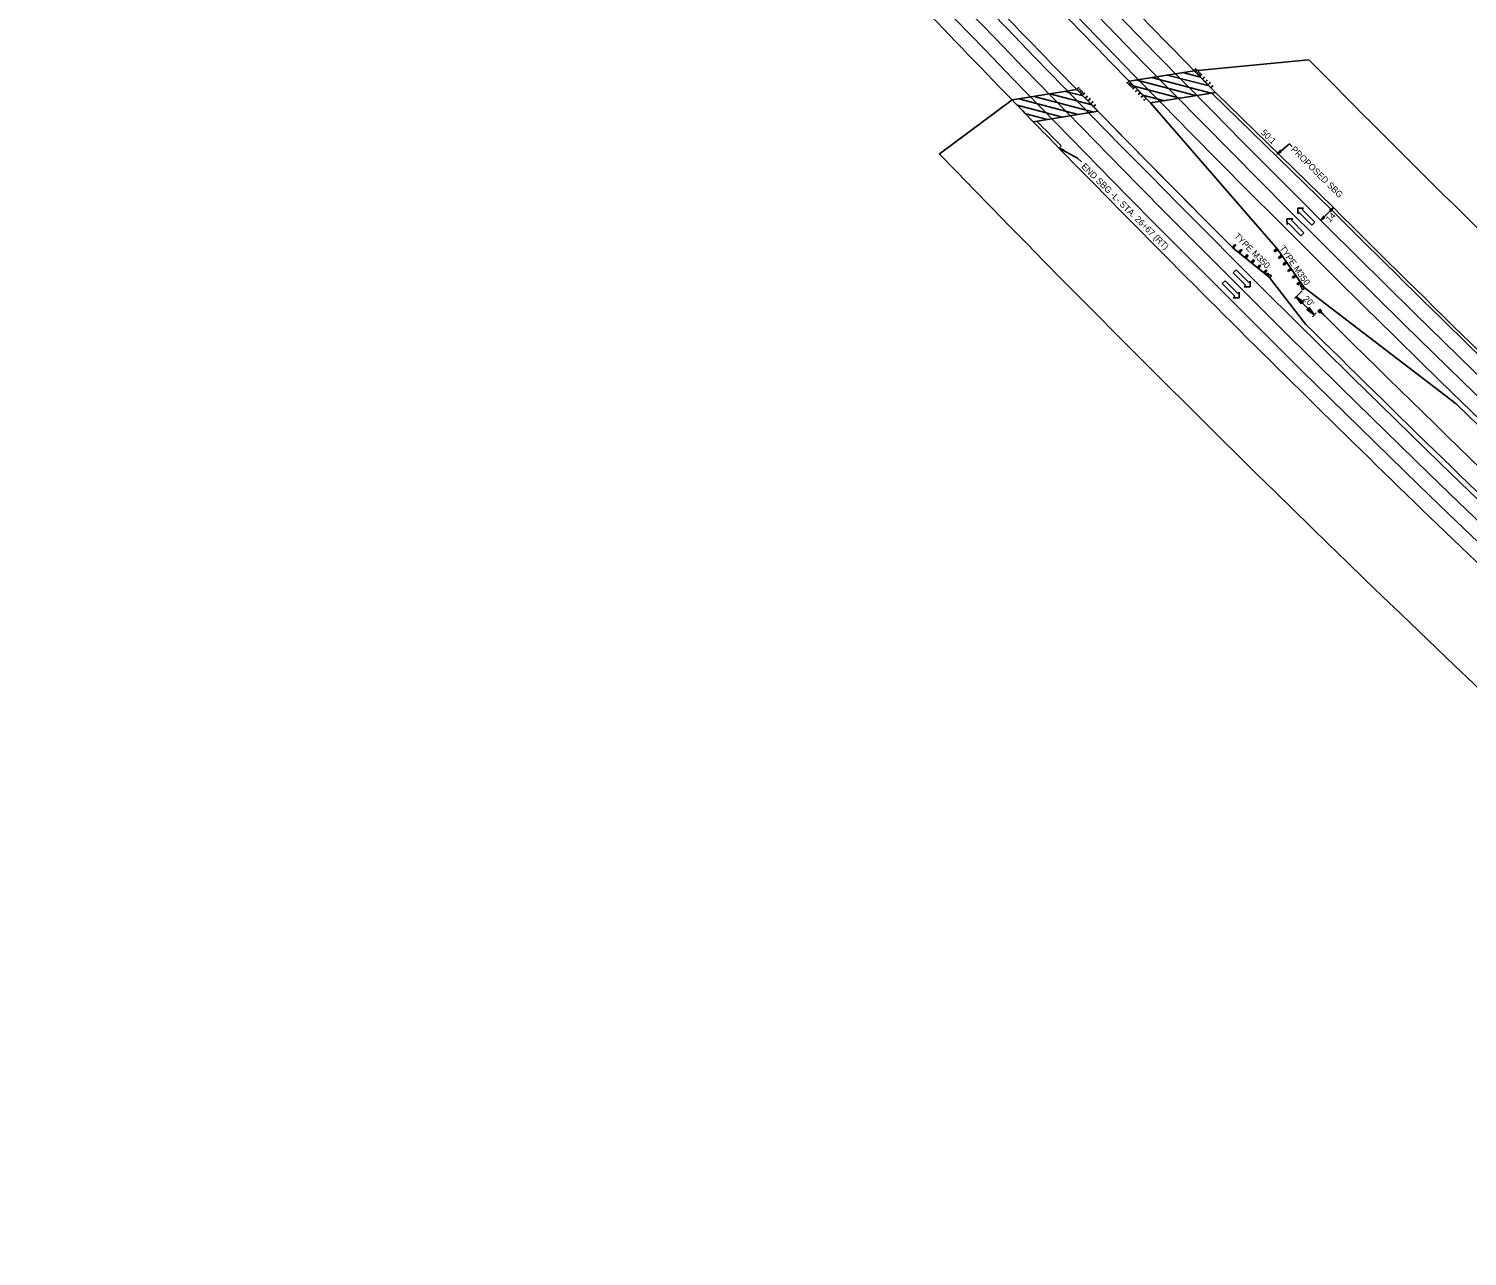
# Model space of a CAD drawing. Extents: x 1602193 to 1605074, y 908180 to 910630.
# Drawn here: x 1602527 to 1603654, y 908258 to 909219 of the extents above; entities that cross this region are included whole.
import ezdxf

# ---------------------------------------------------------------- set-up
doc = ezdxf.new("R2010")
doc.units = 0
for name, color, linetype in [('Prop Approach Slab', 7, 'Continuous'), ('Prop Approach Slab Hatching', 7, 'Continuous'), ('Prop Cable Guiderail Anchor Unit CELL', 7, 'Continuous'), ('Prop Cable Guiderail Double Face', 7, 'Continuous'), ('Prop Conc Shoulder Berm Gutter', 7, 'Continuous'), ('Prop Dimension', 7, 'Continuous'), ('Prop Dimension Text', 7, 'Continuous'), ('Prop DSN Text', 7, 'Continuous'), ('Prop EOT', 7, 'Continuous'), ('Prop Fence Woven Wire', 7, 'Continuous'), ('Prop Guardrail', 7, 'Continuous'), ('Prop Guardrail Anchor Unit CELL', 7, 'Continuous'), ('Prop Lane Arrow CELL', 7, 'Continuous'), ('Prop Lane Lines', 7, 'Continuous'), ('Prop Paved Shoulder', 7, 'Continuous'), ('Prop Roadway Bridge', 7, 'Continuous'), ('Prop Structure Anchor Unit CELL', 7, 'Continuous'), ('Prop Terminator CELL', 7, 'Continuous')]:
    doc.layers.add(name, color=color, linetype=linetype)

msp = doc.modelspace()

# ---------------------------------------------------------------- linework, layer by layer
at = {"layer": 'Prop Approach Slab'}
for p, q in [((1603456.6, 909169.3), (1603405.8, 909161.1)), ((1603364.7, 909154.5), (1603314, 909146.3))]:
    msp.add_line(p, q, dxfattribs=at)
for radius, start, end in [(14299.9, 224.45944, 224.55525), (14341.9, 224.34066, 224.43605), (14417.9, 224.12792, 224.22258), (14375.9, 224.24514, 224.34021)]:
    msp.add_arc((1613646.3, 919202), radius, start, end, dxfattribs=at)
at = {"layer": 'Prop Approach Slab Hatching'}
for p, q in [((1603392.9, 909174.2), (1603428.8, 909164.8)), ((1603394.3, 909179), (1603441, 909166.8)), ((1603406.5, 909181), (1603453.2, 909168.7)), ((1603418.7, 909182.9), (1603451.6, 909174.3)), ((1603431, 909184.9), (1603444.8, 909181.3)), ((1603302.5, 909164.2), (1603349.2, 909152)), ((1603314.7, 909166.2), (1603361.4, 909153.9)), ((1603326.9, 909168.1), (1603359.7, 909159.5)), ((1603339.1, 909170.1), (1603352.9, 909166.5)), ((1603399.7, 909167.2), (1603416.6, 909162.8)), ((1603301.2, 909159.4), (1603336.9, 909150)), ((1603308, 909152.4), (1603324.7, 909148))]:
    msp.add_line(p, q, dxfattribs=at)
at = {"layer": 'Prop Cable Guiderail Anchor Unit CELL'}
for p, q in [((1603536.9, 908998), (1603538.3, 908999.4)), ((1603536.9, 908998), (1603538.4, 908996.6)), ((1603537.9, 908997.9), (1603538.5, 908998.5)), ((1603537.9, 908997.9), (1603538.2, 908997.5)), ((1603538.2, 908997.5), (1603538.8, 908998.1)), ((1603544, 908992.4), (1603538.2, 908997.9)), ((1603538.3, 908999.4), (1603539.8, 908998)), ((1603544, 908992.4), (1603538.3, 908998)), ((1603538.4, 908996.6), (1603539.8, 908998)), ((1603538.5, 908998.5), (1603538.8, 908998.1)), ((1603544, 908992.4), (1603538.5, 908998.1)), ((1603555.4, 908981.1), (1603544, 908992.4)), ((1603544, 908992.4), (1603544, 908992.4))]:
    msp.add_line(p, q, dxfattribs=at)
at = {"layer": 'Prop Cable Guiderail Double Face'}
msp.add_arc((1613646.3, 919202), 14362.9, 225.3666, 228.62871, dxfattribs=at)
at = {"layer": 'Prop Conc Shoulder Berm Gutter'}
msp.add_line((1603456.6, 909169.3), (1603549.1, 909079), dxfattribs=at)
for radius, start, end in [(14417.9, 224.22258, 224.33714), (14297.9, 225.07288, 227.66114)]:
    msp.add_arc((1613646.3, 919202), radius, start, end, dxfattribs=at)
at = {"layer": 'Prop Dimension'}
for p, q in [((1603524.4, 909013.8), (1603518.4, 909007.8)), ((1603535.5, 908996.6), (1603532.6, 908993.6))]:
    msp.add_line(p, q, dxfattribs=at)
msp.add_arc((1613646.3, 919202), 14368, 225.18707, 225.26688, dxfattribs=at)
at = {"layer": 'Prop Dimension Text'}
msp.add_line((1603539.2, 909069.1), (1603549.1, 909079), dxfattribs=at)
at = {"layer": 'Prop DSN Text'}
for p, q in [((1603504.9, 909121), (1603514.6, 909129)), ((1603514.6, 909129), (1603516.7, 909127)), ((1603334.1, 909125.7), (1603348.6, 909117.8)), ((1603351.7, 909114.8), (1603348.6, 909117.8))]:
    msp.add_line(p, q, dxfattribs=at)
for points in [[(1603337.1, 909123.3), (1603334.1, 909125.7), (1603337.7, 909124.4), (1603337, 909124.1)], [(1603508.3, 909122.9), (1603504.9, 909121), (1603507.4, 909123.9), (1603507.5, 909123.1)], [(1603545.9, 909076.8), (1603549.1, 909079), (1603546.8, 909075.9), (1603546.7, 909076.7)], [(1603542.3, 909071.3), (1603539.2, 909069.1), (1603541.4, 909072.3), (1603541.5, 909071.5)]]:
    msp.add_lwpolyline(points, close=True, dxfattribs=at)
at = {"layer": 'Prop EOT'}
for radius, start, end in [(14311.9, 219.48088, 227.66114), (14335.9, 219.48098, 227.66104), (14381.9, 219.48098, 227.66104), (14405.9, 219.47972, 227.6623)]:
    msp.add_arc((1613646.3, 919202), radius, start, end, dxfattribs=at)
at = {"layer": 'Prop Fence Woven Wire'}
for p, q in [((1603439.8, 909186.3), (1603529.6, 909194.9)), ((1603297.4, 909163.4), (1603240.2, 909121))]:
    msp.add_line(p, q, dxfattribs=at)
for centre, radius, start, end in [((1613600.3, 919154.7), 14163.9, 224.68305, 227.26896), ((1613603.1, 919154.1), 14423.9, 224.0735, 229.06345)]:
    msp.add_arc(centre, radius, start, end, dxfattribs=at)
at = {"layer": 'Prop Guardrail'}
for p, q in [((1603549.1, 909079), (1603456.6, 909169.3)), ((1603405.8, 909161.1), (1603505.1, 909046.5))]:
    msp.add_line(p, q, dxfattribs=at)
for radius, start, end in [(14341.9, 224.41557, 224.43605), (14299.9, 224.53456, 224.55525), (14375.9, 224.31987, 224.939), (14297.9, 225.07288, 227.66114)]:
    msp.add_arc((1613646.3, 919202), radius, start, end, dxfattribs=at)
at = {"layer": 'Prop Guardrail Anchor Unit CELL'}
for p, q in [((1603469.8, 909047.9), (1603471.7, 909050.2)), ((1603471.6, 909048.4), (1603471.7, 909050.2)), ((1603471.7, 909050.2), (1603472.5, 909049.5)), ((1603469.8, 909047.9), (1603471.6, 909048.4)), ((1603470.2, 909047.6), (1603496.9, 909026)), ((1603470.6, 909047.2), (1603472.5, 909049.5)), ((1603470.8, 909049), (1603470.6, 909047.2)), ((1603472.5, 909049.5), (1603470.8, 909049)), ((1603470.8, 909049), (1603471.6, 909048.4)), ((1603474.7, 909043.9), (1603476.6, 909046.2)), ((1603474.7, 909043.9), (1603476.5, 909044.4)), ((1603475.5, 909043.3), (1603477.4, 909045.6)), ((1603475.7, 909045.1), (1603475.5, 909043.3)), ((1603477.4, 909045.6), (1603475.7, 909045.1)), ((1603475.7, 909045.1), (1603476.5, 909044.4)), ((1603476.5, 909044.4), (1603476.6, 909046.2)), ((1603476.6, 909046.2), (1603477.4, 909045.6)), ((1603479.6, 909039.9), (1603481.5, 909042.2)), ((1603479.6, 909039.9), (1603481.3, 909040.5)), ((1603480.4, 909039.3), (1603482.3, 909041.6)), ((1603480.6, 909041.1), (1603480.4, 909039.3)), ((1603482.3, 909041.6), (1603480.6, 909041.1)), ((1603480.6, 909041.1), (1603481.3, 909040.5)), ((1603481.3, 909040.5), (1603481.5, 909042.2)), ((1603481.5, 909042.2), (1603482.3, 909041.6)), ((1603504.8, 909046.9), (1603502.4, 909045.2)), ((1603504.2, 909045.2), (1603502.4, 909045.2)), ((1603502.4, 909045.2), (1603503, 909044.4)), ((1603505.4, 909046.1), (1603503, 909044.4)), ((1603503, 909044.4), (1603503.6, 909046)), ((1603503.6, 909046), (1603505.4, 909046.1)), ((1603503.6, 909046), (1603504.2, 909045.2)), ((1603504.8, 909046.9), (1603504.2, 909045.2)), ((1603505.1, 909046.5), (1603524.7, 909018.3)), ((1603508.4, 909041.7), (1603506, 909040)), ((1603507.8, 909040), (1603506, 909040)), ((1603506, 909040), (1603506.6, 909039.2)), ((1603509, 909040.9), (1603506.6, 909039.2)), ((1603506.6, 909039.2), (1603507.2, 909040.8)), ((1603507.2, 909040.8), (1603509, 909040.9)), ((1603507.2, 909040.8), (1603507.8, 909040)), ((1603508.4, 909041.7), (1603507.8, 909040)), ((1603484.5, 909036), (1603486.4, 909038.3)), ((1603484.5, 909036), (1603486.2, 909036.5)), ((1603485.3, 909035.4), (1603487.1, 909037.6)), ((1603485.5, 909037.1), (1603485.3, 909035.4)), ((1603487.1, 909037.6), (1603485.5, 909037.1)), ((1603485.5, 909037.1), (1603486.2, 909036.5)), ((1603486.2, 909036.5), (1603486.4, 909038.3)), ((1603486.4, 909038.3), (1603487.1, 909037.6)), ((1603489.4, 909032), (1603491.3, 909034.3)), ((1603489.4, 909032), (1603491.1, 909032.6)), ((1603490.2, 909031.4), (1603492, 909033.7)), ((1603490.4, 909033.2), (1603490.2, 909031.4)), ((1603492, 909033.7), (1603490.4, 909033.2)), ((1603490.4, 909033.2), (1603491.1, 909032.6)), ((1603491.1, 909032.6), (1603491.3, 909034.3)), ((1603491.3, 909034.3), (1603492, 909033.7)), ((1603494.3, 909028.1), (1603496.2, 909030.3)), ((1603494.3, 909028.1), (1603496, 909028.6)), ((1603494.7, 909027.7), (1603495.2, 909028.3)), ((1603495.1, 909027.4), (1603496.9, 909029.7)), ((1603495.3, 909029.2), (1603495.1, 909027.4)), ((1603496.9, 909029.7), (1603495.3, 909029.2)), ((1603495.3, 909029.2), (1603496, 909028.6)), ((1603496, 909028.6), (1603496.2, 909030.3)), ((1603496.2, 909030.3), (1603496.9, 909029.7)), ((1603497.4, 909027.7), (1603496.4, 909026.4)), ((1603498.5, 909026.8), (1603497.4, 909027.7)), ((1603497.4, 909025.5), (1603497.4, 909027.7)), ((1603512, 909036.5), (1603509.6, 909034.9)), ((1603511.4, 909034.9), (1603509.6, 909034.9)), ((1603509.6, 909034.9), (1603510.2, 909034)), ((1603512.6, 909035.7), (1603510.2, 909034)), ((1603510.2, 909034), (1603510.8, 909035.7)), ((1603510.8, 909035.7), (1603511.4, 909034.9)), ((1603510.8, 909035.7), (1603512.6, 909035.7)), ((1603512, 909036.5), (1603511.4, 909034.9)), ((1603515.6, 909031.4), (1603513.2, 909029.7)), ((1603515, 909029.7), (1603513.2, 909029.7)), ((1603513.2, 909029.7), (1603513.8, 909028.9)), ((1603516.2, 909030.5), (1603513.8, 909028.9)), ((1603513.8, 909028.9), (1603514.4, 909030.5)), ((1603514.4, 909030.5), (1603515, 909029.7)), ((1603514.4, 909030.5), (1603516.2, 909030.5)), ((1603515.6, 909031.4), (1603515, 909029.7)), ((1603496.4, 909026.4), (1603498.5, 909026.8)), ((1603496.9, 909026), (1603497.4, 909026.6)), ((1603496.9, 909026), (1603498.6, 909024.6)), ((1603497.4, 909025.5), (1603498.5, 909026.8)), ((1603497.4, 909025.5), (1603497.9, 909026.1)), ((1603497.4, 909025.5), (1603497.9, 909026.1)), ((1603499, 909026.3), (1603497.9, 909026.1)), ((1603519.2, 909026.2), (1603516.8, 909024.5)), ((1603518.6, 909024.5), (1603516.8, 909024.5)), ((1603516.8, 909024.5), (1603517.4, 909023.7)), ((1603519.8, 909025.4), (1603517.4, 909023.7)), ((1603517.4, 909023.7), (1603518, 909025.3)), ((1603518, 909025.3), (1603519.8, 909025.4)), ((1603518, 909025.3), (1603518.6, 909024.5)), ((1603519.2, 909026.2), (1603518.6, 909024.5)), ((1603522.8, 909021), (1603520.4, 909019.3)), ((1603522.2, 909019.3), (1603520.4, 909019.3)), ((1603520.4, 909019.3), (1603521, 909018.5)), ((1603523.4, 909020.2), (1603521, 909018.5)), ((1603521, 909018.5), (1603521.6, 909020.2)), ((1603521.6, 909020.2), (1603522.2, 909019.3)), ((1603521.6, 909020.2), (1603523.4, 909020.2)), ((1603522.8, 909021), (1603522.2, 909019.3)), ((1603523.1, 909020.6), (1603522.5, 909020.2)), ((1603523, 909018), (1603524.3, 909018.9)), ((1603523.8, 909016.8), (1603523, 909018)), ((1603525.1, 909017.7), (1603523, 909018)), ((1603524.3, 909018.9), (1603523.8, 909016.8)), ((1603525.1, 909017.7), (1603523.8, 909016.8)), ((1603524.7, 909018.3), (1603524, 909017.8)), ((1603524.2, 909016.2), (1603524.5, 909017.3)), ((1603525.1, 909017.7), (1603524.5, 909017.3)), ((1603525.1, 909017.7), (1603524.5, 909017.3)), ((1603524.7, 909018.3), (1603526, 909016.5))]:
    msp.add_line(p, q, dxfattribs=at)
for centre, major_axis, start_param, end_param in [((1603499.2, 909025.4), (0.625, 0.772), 3.141593, 7.214552), ((1603525.1, 909015.9), (0.815, 0.567), 2.210226, 6.283185)]:
    msp.add_ellipse(centre, major_axis=major_axis, ratio=0.995379, start_param=start_param, end_param=end_param, dxfattribs=at)
at = {"layer": 'Prop Lane Arrow CELL'}
for p, q in [((1603521.1, 909074.3), (1603521.1, 909078.7)), ((1603521.1, 909078.7), (1603525.6, 909078.7)), ((1603522.2, 909075.3), (1603521.1, 909074.3)), ((1603532.1, 909065.4), (1603522.2, 909075.3)), ((1603525.6, 909078.7), (1603524.5, 909077.6)), ((1603524.5, 909077.6), (1603534.4, 909067.7)), ((1603512.7, 909065.8), (1603512.6, 909070.2)), ((1603512.6, 909070.2), (1603517.1, 909070.2)), ((1603513.7, 909066.8), (1603512.7, 909065.8)), ((1603523.6, 909056.9), (1603513.7, 909066.8)), ((1603517.1, 909070.2), (1603516.1, 909069.2)), ((1603516.1, 909069.2), (1603525.9, 909059.2)), ((1603534.4, 909067.7), (1603532.1, 909065.4)), ((1603525.9, 909059.2), (1603523.6, 909056.9)), ((1603470.4, 909028), (1603472.8, 909030.3)), ((1603480.3, 909018.1), (1603470.4, 909028)), ((1603472.8, 909030.3), (1603482.7, 909020.4)), ((1603461.8, 909019.5), (1603464.2, 909021.8)), ((1603471.7, 909009.6), (1603461.8, 909019.5)), ((1603464.2, 909021.8), (1603474, 909011.9)), ((1603479.2, 909017), (1603480.3, 909018.1)), ((1603483.7, 909017.1), (1603479.2, 909017)), ((1603482.7, 909020.4), (1603483.7, 909021.5)), ((1603483.7, 909021.5), (1603483.7, 909017.1)), ((1603470.6, 909008.5), (1603471.7, 909009.6)), ((1603475.1, 909008.5), (1603470.6, 909008.5)), ((1603474, 909011.9), (1603475.1, 909012.9)), ((1603475.1, 909012.9), (1603475.1, 909008.5))]:
    msp.add_line(p, q, dxfattribs=at)
at = {"layer": 'Prop Lane Lines'}
for radius in [14323.9, 14393.9]:
    msp.add_arc((1613646.3, 919202), radius, 219.48098, 227.66104, dxfattribs=at)
at = {"layer": 'Prop Paved Shoulder'}
for p, q in [((1603453.7, 909168.8), (1603547.4, 909077.4)), ((1603405.8, 909161.1), (1603505.1, 909046.5)), ((1603334.1, 909125.7), (1603335.7, 909127.3)), ((1603470.2, 909047.6), (1603498.6, 909024.6)), ((1603505.1, 909046.5), (1603526, 909016.5)), ((1603498.6, 909024.6), (1603527.5, 908987.6)), ((1603526, 909016.5), (1603645.1, 908925.4))]:
    msp.add_line(p, q, dxfattribs=at)
for radius, start, end in [(14375.9, 224.34021, 224.939), (14415.5, 224.22909, 224.33714), (14417.9, 224.33714, 226.46447), (14300.2, 225.07288, 227.66104), (14377.9, 225.26931, 227.66083), (14339.9, 225.77799, 227.66104)]:
    msp.add_arc((1613646.3, 919202), radius, start, end, dxfattribs=at)
at = {"layer": 'Prop Roadway Bridge'}
for p, q in [((1603439.8, 909186.3), (1603389.1, 909178.1)), ((1603348, 909171.5), (1603297.4, 909163.4))]:
    msp.add_line(p, q, dxfattribs=at)
for radius, start, end in [(14299.9, 224.00576, 224.45944), (14375.9, 223.79503, 224.24514), (14341.9, 223.88896, 224.34066), (14417.9, 223.67976, 224.12792)]:
    msp.add_arc((1613646.3, 919202), radius, start, end, dxfattribs=at)
at = {"layer": 'Prop Structure Anchor Unit CELL'}
for p, q in [((1603439.8, 909186.3), (1603441.3, 909187.7)), ((1603439.8, 909186.3), (1603453, 909172.9)), ((1603440.9, 909188.1), (1603441.7, 909187.3)), ((1603440.9, 909185.2), (1603442.4, 909186.6)), ((1603442, 909187), (1603442.8, 909186.2)), ((1603442, 909184.1), (1603443.4, 909185.5)), ((1603443, 909185.9), (1603443.8, 909185.1)), ((1603387.2, 909177.2), (1603388, 909176.3)), ((1603389.1, 909178.1), (1603387.6, 909176.7)), ((1603388.3, 909176), (1603389.1, 909175.2)), ((1603390.1, 909177), (1603388.7, 909175.6)), ((1603389.1, 909178.1), (1603402.2, 909164.7)), ((1603389.4, 909174.9), (1603390.2, 909174.1)), ((1603391.2, 909175.9), (1603389.8, 909174.5)), ((1603390.5, 909173.8), (1603391.3, 909173)), ((1603392.3, 909174.8), (1603390.9, 909173.4)), ((1603443.1, 909183), (1603444.5, 909184.4)), ((1603444.1, 909184.8), (1603444.9, 909184)), ((1603444.2, 909181.9), (1603445.6, 909183.3)), ((1603445.2, 909183.7), (1603446, 909182.9)), ((1603446.4, 909179.6), (1603447.8, 909181)), ((1603447.4, 909181.4), (1603448.2, 909180.6)), ((1603448.6, 909177.4), (1603450, 909178.8)), ((1603449.6, 909179.2), (1603450.4, 909178.4)), ((1603450.8, 909175.2), (1603452.2, 909176.6)), ((1603451.8, 909177), (1603452.6, 909176.2)), ((1603453, 909172.9), (1603454.4, 909174.3)), ((1603454, 909174.8), (1603454.8, 909173.9)), ((1603348, 909171.5), (1603349.4, 909172.9)), ((1603348, 909171.5), (1603361.1, 909158.1)), ((1603349, 909173.3), (1603349.8, 909172.5)), ((1603349.1, 909170.4), (1603350.5, 909171.8)), ((1603350.1, 909172.2), (1603350.9, 909171.4)), ((1603350.2, 909169.3), (1603351.6, 909170.7)), ((1603351.2, 909171.1), (1603352, 909170.3)), ((1603351.3, 909168.2), (1603352.7, 909169.6)), ((1603352.3, 909170), (1603353.1, 909169.2)), ((1603352.4, 909167.1), (1603353.8, 909168.5)), ((1603353.4, 909168.9), (1603354.2, 909168)), ((1603354.5, 909164.8), (1603356, 909166.2)), ((1603355.6, 909166.6), (1603356.4, 909165.8)), ((1603356.7, 909162.6), (1603358.2, 909164)), ((1603357.8, 909164.4), (1603358.6, 909163.6)), ((1603391.6, 909172.7), (1603392.4, 909171.9)), ((1603393.4, 909173.7), (1603392, 909172.3)), ((1603393.8, 909170.5), (1603394.6, 909169.6)), ((1603395.6, 909171.4), (1603394.2, 909170)), ((1603396, 909168.2), (1603396.8, 909167.4)), ((1603397.8, 909169.2), (1603396.4, 909167.8)), ((1603398.1, 909166), (1603399, 909165.2)), ((1603400, 909167), (1603398.6, 909165.6)), ((1603400.3, 909163.8), (1603401.1, 909162.9)), ((1603402.2, 909164.7), (1603400.7, 909163.3)), ((1603358.9, 909160.4), (1603360.3, 909161.7)), ((1603359.9, 909162.2), (1603360.7, 909161.3)), ((1603361.1, 909158.1), (1603362.5, 909159.5)), ((1603362.1, 909159.9), (1603362.9, 909159.1))]:
    msp.add_line(p, q, dxfattribs=at)
at = {"layer": 'Prop Terminator CELL'}
for points in [[(1603523.8, 909003.6), (1603519.8, 909009.2), (1603525.5, 909005.3), (1603524, 909005)], [(1603523.8, 909003.6), (1603519.8, 909009.2), (1603525.5, 909005.3), (1603524, 909005)], [(1603530.1, 909000.7), (1603534, 908995.1), (1603528.4, 908999), (1603529.8, 908999.3)]]:
    msp.add_lwpolyline(points, close=True, dxfattribs=at)

# ---------------------------------------------------------------- texts
at = {"layer": 'Prop Dimension'}
msp.add_text("20'", height=5, rotation=315.2267, dxfattribs=at).set_placement((1603524.8, 909007.1))
at = {"layer": 'Prop Dimension Text'}
for s, rotation, p in [('50:1', 315.701, (1603491.8, 909137.3)), ("14'", 45.0729, (1603546, 909067.1))]:
    msp.add_text(s, height=5, rotation=rotation, dxfattribs=at).set_placement(p)
at = {"layer": 'Prop DSN Text'}
for s, p in [('PROPOSED SBG', (1603515.3, 909124.1)), ('END SBG -L- STA. 26+67 (RT)', (1603351.2, 909110.8))]:
    msp.add_text(s, height=5, rotation=315.2976, dxfattribs=at).set_placement(p)
at = {"layer": 'Prop Guardrail Anchor Unit CELL'}
for rotation, p in [(315.2976, (1603470.8, 909056.2)), (304.6646, (1603506.5, 909047.2))]:
    msp.add_text('TYPE M350', height=5, rotation=rotation, dxfattribs=at).set_placement(p)

doc.saveas('drawing.dxf')
